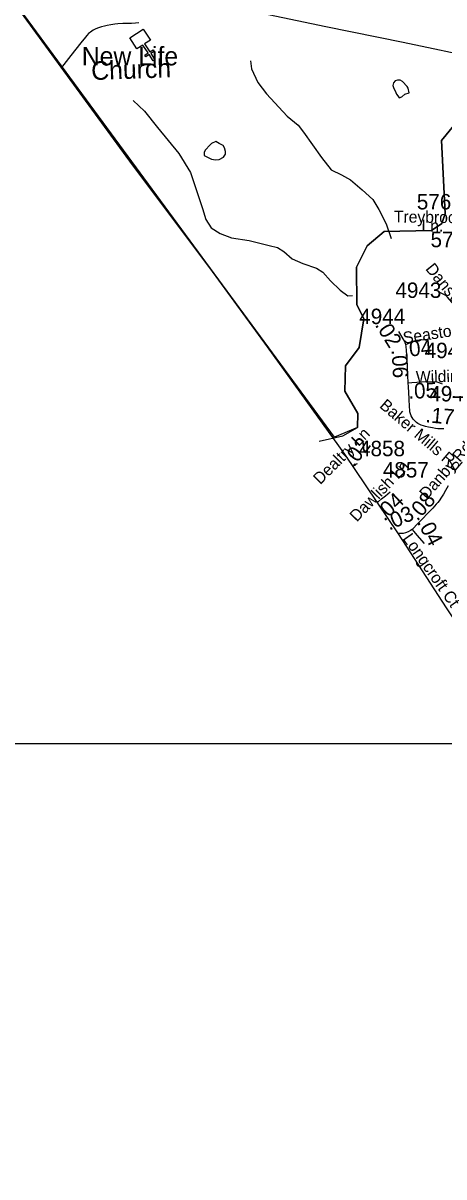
# Model space of a CAD drawing. Extents: x 1383679 to 1536984, y 460658 to 651027.
# Drawn here: x 1433431 to 1436839, y 473807 to 483158 of the extents above; entities that cross this region are included whole.
import ezdxf

# ---------------------------------------------------------------- set-up
doc = ezdxf.new("R2010")
doc.units = 0
for name, color, linetype in [('Exist Boundary Political City Limit New', 7, 'Continuous'), ('Exist Boundary Political StateLine', 7, 'Continuous'), ('Exist Cultural Church CELL', 7, 'Continuous'), ('Exist Cultural Church Label', 7, 'Continuous'), ('Exist Hydrographic Creek Single Shore', 7, 'Continuous'), ('Exist Hydrographic Misc Water Feature', 7, 'Continuous'), ('Exist Road Secondary Mileage Hundredths English Label', 7, 'Continuous'), ('Exist Road Secondary Type 51 Attributed', 7, 'Continuous'), ('Exist Road Secondary Type 51 Label', 7, 'Continuous'), ('Exist Road Secondary Type 51 Number Label', 7, 'Continuous'), ('Exist Utilities Electrical Transmission Line', 7, 'Continuous'), ('Map Preparation Boundary City Limit Buffer Line', 7, 'Continuous'), ('Map Preparation Inset Cut Line', 7, 'Continuous')]:
    doc.layers.add(name, color=color, linetype=linetype)

msp = doc.modelspace()

# ---------------------------------------------------------------- linework, layer by layer
at = {"layer": 'Exist Boundary Political City Limit New'}
msp.add_lwpolyline([(1437439.1, 483271), (1437284.1, 483034.5), (1437214.1, 482835.8), (1436980.1, 482403.9), (1436818.1, 482207), (1436848.1, 481615.5), (1436822, 481533.9), (1436737, 481476.6), (1436354.1, 481467.9), (1436218.1, 481352.4), (1436131.1, 481180.2), (1436133.1, 480878.2), (1436190.1, 480762.2), (1436152.1, 480529.9), (1436041.1, 480381.1), (1436036.1, 480174.4), (1436141.1, 479995.1), (1436139.1, 479880.2), (1435952, 479801.4), (1430224.2, 487598.4)], dxfattribs=at)
at = {"layer": 'Exist Boundary Political StateLine'}
msp.add_lwpolyline([(1443385.7, 468860.6), (1442857.3, 469616.4), (1442270.4, 470457.6), (1441736.3, 471231.7), (1441054.2, 472226.4), (1440397.5, 473190.9), (1439900.4, 473912.2), (1439582.6, 474364.2), (1438883, 475385.3), (1438491.3, 475964.4), (1438054.4, 476617.4), (1437668.2, 477203.2), (1436861, 478419.8), (1436471, 479017.8), (1436036, 479664.8), (1435409.6, 480533.7), (1434942.5, 481173.4), (1434317.4, 482010.1), (1433106.8, 483665.1)], dxfattribs=at)
at = {"layer": 'Exist Cultural Church CELL'}
msp.add_lwpolyline([(1434462.7, 483019.9), (1434415, 482988.8), (1434456.5, 482924.9), (1434483.4, 482942.4), (1434492.1, 482929), (1434465.2, 482911.5), (1434498, 482861.1), (1434484.5, 482852.4), (1434451.8, 482902.8), (1434424.9, 482885.4), (1434416.2, 482898.8), (1434443.1, 482916.2), (1434401.6, 482980.1), (1434353.2, 482948.8), (1434295.2, 483038), (1434404.8, 483109.2)], close=True, dxfattribs=at)
at = {"layer": 'Exist Hydrographic Creek Single Shore'}
msp.add_lwpolyline([(1435828.9, 479768.5), (1436021.1, 479813.7), (1436139.1, 479880.2), (1436141.1, 479995.1), (1436036.1, 480174.4), (1436041.1, 480381.1), (1436152.1, 480529.9), (1436190.1, 480762.2), (1436133.1, 480878.2), (1436131.1, 481180.2), (1436218.1, 481352.4), (1436354.1, 481467.9), (1436737.1, 481476.6), (1436822.1, 481533.9), (1436848.1, 481615.5), (1436818.2, 482207), (1436980.2, 482403.9), (1437214.1, 482835.8), (1437284.1, 483034.5), (1437439.2, 483271)], dxfattribs=at)
at = {"layer": 'Exist Hydrographic Misc Water Feature'}
for points in [[(1435271.8, 482852.6), (1435280.5, 482786.8), (1435332.3, 482675.8), (1435402.5, 482584.1), (1435569.2, 482402.7), (1435657.8, 482331.1), (1435702.7, 482274.5), (1435848.7, 482069.7), (1435924.9, 481969.6), (1436010.1, 481927.7), (1436083.3, 481888.5), (1436175.8, 481807), (1436264.2, 481727.3), (1436312.7, 481648.4), (1436370.5, 481530.7), (1436412.2, 481411.7)], [(1436557.4, 482593.7), (1436548, 482631.7), (1436540.4, 482644.1), (1436503, 482685.1), (1436483.2, 482695.3), (1436463.3, 482695.7), (1436443.2, 482690.3), (1436430.9, 482674.2), (1436424.5, 482652.2), (1436432, 482626.6), (1436443.6, 482609.9), (1436455.1, 482581.8), (1436466.8, 482569.3), (1436476.5, 482553.5), (1436496.7, 482561.3), (1436523, 482582.1), (1436557.4, 482593.7)], [(1434323, 482529.5), (1434413.3, 482443.2), (1434518.8, 482311.4), (1434692.8, 482102), (1434785.9, 481948.3), (1434884.2, 481655.8), (1434910.5, 481565), (1434955.2, 481498.4), (1435028.3, 481452.7), (1435119.6, 481418.8), (1435261.3, 481394.6), (1435422.6, 481355.3), (1435492.3, 481338.3), (1435543.7, 481306.9), (1435610.6, 481247.3), (1435695.9, 481210.3), (1435807.2, 481171.9), (1435858.7, 481140.5), (1435921.3, 481069.5), (1435999.8, 480994.1), (1436060.9, 480948.5), (1436099.1, 480950.2)], [(1434992.9, 482197.7), (1434956.5, 482181.2), (1434942.3, 482169.2), (1434909.5, 482132), (1434897.1, 482111.8), (1434896.8, 482096.2), (1434898.6, 482085.5), (1434956, 482054.8), (1434990.1, 482050), (1435018, 482051.1), (1435054.4, 482070.9), (1435068.9, 482094.4), (1435071.3, 482116.5), (1435061.9, 482147), (1435050.3, 482165.3), (1435018.6, 482181.6), (1434992.9, 482197.7)]]:
    msp.add_lwpolyline(points, dxfattribs=at)
at = {"layer": 'Exist Road Secondary Type 51 Attributed'}
for points in [[(1434367.4, 483158.8), (1434340.8, 483157), (1434307.8, 483155.7), (1434237.8, 483154.5), (1434197.5, 483152), (1434173.9, 483149.4), (1434140.6, 483144.8), (1434111.6, 483139), (1434090.5, 483133.6), (1434066.3, 483127.9), (1434041.7, 483120.1), (1434020.6, 483111.4), (1433999.3, 483100), (1433976.1, 483084.7), (1433962, 483072.5), (1433947.9, 483058.4), (1433935.4, 483044), (1433898.9, 482999.2), (1433858, 482946), (1433818.7, 482895.5), (1433741.2, 482797.9)], [(1437174.1, 480509), (1437172.2, 480519), (1437164.3, 480545.2), (1437154.8, 480572.4), (1437146.3, 480594.4), (1437135.8, 480615.8), (1437124.5, 480635.9), (1437112.4, 480655.1), (1437098.8, 480673.3), (1437068.8, 480707.6), (1436868.3, 480936.8), (1436853, 480951), (1436794.1, 480980)], [(1436529.3, 480553.5), (1436528.3, 480558.2), (1436521.4, 480576.9), (1436509.2, 480600), (1436473.2, 480658)], [(1436529.3, 480553.5), (1436581.1, 480574.1), (1436605.9, 480583.2), (1436615.6, 480586.5), (1436625.8, 480588.8), (1436638.6, 480590.8), (1436652, 480592), (1436674, 480593.3), (1436713.7, 480592.5)], [(1436550.4, 480242.4), (1436547.8, 480302.8), (1436544.8, 480370.9), (1436541.3, 480437.2), (1436537, 480505.2), (1436532.7, 480537.8), (1436529.3, 480553.5)], [(1436550.4, 480242.4), (1436578.9, 480245.2), (1436658.9, 480249.3), (1436773.6, 480253.8), (1436798.3, 480246.1), (1436825, 480234.8)], [(1436839.1, 479870.7), (1436821.4, 479869.8), (1436805, 479869.8), (1436788.4, 479870.9), (1436769.3, 479872.7), (1436745, 479876.9), (1436713.1, 479884), (1436689.7, 479889.6), (1436674.7, 479893.1), (1436655.6, 479899.8), (1436639.2, 479907), (1436628.8, 479913.7), (1436617.2, 479922.2), (1436603.1, 479934.9), (1436590.8, 479948.9), (1436582.3, 479961.7), (1436574.8, 479975), (1436568, 479990.8), (1436563.8, 480006.8), (1436561.7, 480023.4), (1436559.7, 480045.2), (1436557.1, 480116.7), (1436551.9, 480210.6), (1436550.4, 480242.4)], [(1436101.4, 479567.6), (1436124.1, 479581.9), (1436137.9, 479589.1)], [(1436300.8, 479270.9), (1436309.8, 479279.9), (1436334.6, 479301.8), (1436365.1, 479326.4), (1436404.9, 479359.6)], [(1436872.7, 479408.1), (1436851.1, 479370.4), (1436835.3, 479340.2), (1436820.2, 479314.9), (1436801, 479287.2), (1436789.5, 479272.7), (1436777.2, 479258.9), (1436748, 479227), (1436708.3, 479185.1), (1436663.6, 479138.7), (1436622.4, 479095.7), (1436589.9, 479061.1), (1436581.6, 479054.8)], [(1436581.6, 479054.8), (1436569.2, 479045.4), (1436550.4, 479035.4), (1436526.5, 479026.4), (1436509, 479022.3), (1436490.2, 479020.3), (1436468.5, 479021.5)], [(1436581.6, 479054.8), (1436595.1, 479037.2), (1436620.2, 479007.4), (1436677.7, 478940.9)]]:
    msp.add_lwpolyline(points, dxfattribs=at)
at = {"layer": 'Exist Utilities Electrical Transmission Line'}
msp.add_lwpolyline([(1433072.2, 483712.7), (1433651.4, 483595.3), (1434400.2, 483437.8), (1435069.4, 483299.8), (1435881.8, 483131), (1436509.1, 483004.1), (1437148.5, 482868.8), (1437781.8, 482737.8), (1438363.1, 482613.6), (1438773.3, 482521.1), (1439016.5, 482483.7), (1439560.8, 482377.7), (1440446, 482207.6), (1441293.1, 482028.1), (1442164.2, 481852.1), (1443035.6, 481682.1), (1443460.2, 481596.3), (1443946.4, 481483.5), (1444590.1, 481343.7), (1444822.1, 481229.4), (1445208.7, 481032.3), (1445379.2, 480953), (1445787.7, 480753.5), (1446059.4, 480620.6)], dxfattribs=at)
at = {"layer": 'Map Preparation Boundary City Limit Buffer Line'}
msp.add_lwpolyline([(1437439.1, 483271), (1437284.1, 483034.5), (1437214.1, 482835.8), (1436980.1, 482403.9), (1436818.1, 482207), (1436848.1, 481615.5), (1436822, 481533.9), (1436737, 481476.6), (1436354.1, 481467.9), (1436218.1, 481352.4), (1436131.1, 481180.2), (1436133.1, 480878.2), (1436190.1, 480762.2), (1436152.1, 480529.9), (1436041.1, 480381.1), (1436036.1, 480174.4), (1436141.1, 479995.1), (1436139.1, 479880.2), (1435952, 479801.4), (1430224.2, 487598.4)], dxfattribs=at)
at = {"layer": 'Map Preparation Inset Cut Line'}
msp.add_lwpolyline([(1446195.4, 477316), (1383679.3, 477316), (1383679.3, 520758.2), (1458567.8, 520758.2), (1458567.8, 493672.2), (1446195.4, 493672.2), (1446195.4, 477316)], dxfattribs=at)

# ---------------------------------------------------------------- texts
at = {"layer": 'Exist Cultural Church Label'}
for s, rotation, p in [('New Life', 0.00002, (1433906.4, 482815.1)), ('Church', 2.04705, (1433985.4, 482695.7))]:
    msp.add_text(s, height=150, rotation=rotation, dxfattribs=at).set_placement(p)
at = {"layer": 'Exist Road Secondary Mileage Hundredths English Label'}
for s, rotation, p in [('.02', 301.85985, (1436276.9, 480712)), ('.04', 4.9399, (1436515.4, 480451.7)), ('.06', 273.05524, (1436414.8, 480509.8)), ('.05', 2.24171, (1436553, 480112.5)), ('.17', 354.80535, (1436685.9, 479923.4)), ('.02', 51.71383, (1436110.1, 479554.5)), ('.04', 43.04737, (1436357, 479115.5)), ('.08', 47.99466, (1436623.9, 479115.9)), ('.03', 23.95446, (1436395.1, 479044)), ('.04', 297.70107, (1436618.5, 479113.4))]:
    msp.add_text(s, height=125, rotation=rotation, dxfattribs=at).set_placement(p)
at = {"layer": 'Exist Road Secondary Type 51 Label'}
for s, rotation, p in [('Treybrooke', 359.30918, (1436433.1, 481542.4)), ('Ln.', 359.30918, (1436656.9, 481469.7)), ('Dansville Dr', 308.71841, (1436684.6, 481165)), ('Seastone Ln', 8.88232, (1436515, 480558.7)), ('Wildiris Ct', 1.53397, (1436613.1, 480242.3)), ('Baker Mills Rd', 319.53831, (1436310.9, 480047.4)), ('Dealtry Ln', 44.90491, (1435837.1, 479413.3)), ('Danby Rd', 48.56575, (1436701.4, 479291.7)), ('Dawlish Ln', 46.11628, (1436133.5, 479109.9)), ('Longcroft Ct', 305.07986, (1436500.2, 478980.7))]:
    msp.add_text(s, height=95, rotation=rotation, dxfattribs=at).set_placement(p)
at = {"layer": 'Exist Road Secondary Type 51 Number Label'}
for s, p in [('5763', (1436619.4, 481647.6)), ('5742', (1436730.6, 481341.3)), ('4943', (1436446.2, 480930.7)), ('4944', (1436153.5, 480718.4)), ('4945', (1436683.1, 480442.5)), ('4946', (1436720.5, 480091.7)), ('4858', (1436151.8, 479647.5)), ('4857', (1436344.7, 479475))]:
    msp.add_text(s, height=125, dxfattribs=at).set_placement(p)

doc.saveas('drawing.dxf')
